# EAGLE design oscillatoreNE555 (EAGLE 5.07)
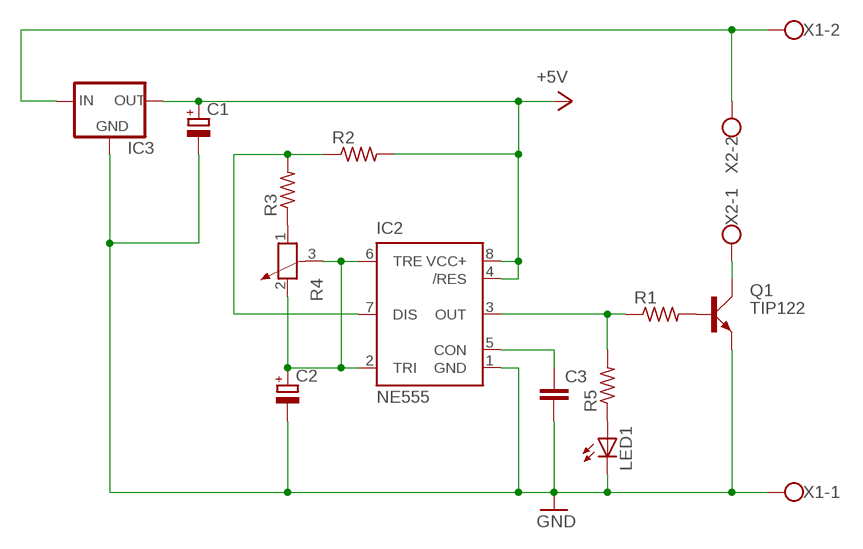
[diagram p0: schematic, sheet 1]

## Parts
C1  CPOL-EUE2.5-7  [E2,5-7]
C2  CPOL-EUE2.5-7  [E2,5-7]
C3  C-EU050-025X075  [C050-025X075]
IC2  NE555  [DIL-08]
IC3  78XXS  [78XXS]
LED1  LED3MM  [LED3MM]
Q1  TIP122  TIP41C  [TO220AV]
R1  R-US_0207/10  [0207/10]
R2  R-US_0207/10  [0207/10]
R3  R-US_0207/10  [0207/10]
R4  POTENTIOMETER_PT-10S  [PT-10S]
R5  R-US_0207/10  [0207/10]
X1  W237-02P  [W237-132]
X2  W237-02P  [W237-132]

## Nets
N$2: Q1.B R1.2
N$3: LED1.A R5.1
N$4: Q1.C X2.1
N$11: C2.+ IC2.2(TRI) IC2.6(TRE) R4.2 R4.3
N$12: R3.1 R4.1
N$13: IC2.7(DIS) R2.1 R3.2
N$17: IC2.3(OUT) R1.1 R5.2
N$19: C3.1 IC2.5(CON)
N$33: IC3.IN X1.2 X2.2
VDD: C1.+ IC2.4(/RES) IC2.8(VCC+) IC3.OUT R2.2 ; supply symbol labelled +5V
VSS: C1.- C2.- C3.2 IC2.1(GND) IC3.GND LED1.K(C) Q1.E X1.1 ; supply symbol labelled GND

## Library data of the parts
C1 C2 = resistor:CPOL-EU: POLARIZED CAPACITOR, European symbol
C3 = resistor:C-EU: CAPACITOR, European symbol
IC2 = st-microelectronics:NE555: General purpose bipolar Timer
IC3 = v-reg:78XXS: VOLTAGE REGULATOR
LED1 = led:LED: LED
Q1 = transistor-power:TIP41C: NPN TRANSISTOR
R1-R3 R5 = resistor:R-US_: RESISTOR, American symbol
R4 = rcl:POTENTIOMETER_: Potentiometer
X1 X2 = con-wago-508:W237-02P: WAGO SREW CLAMP

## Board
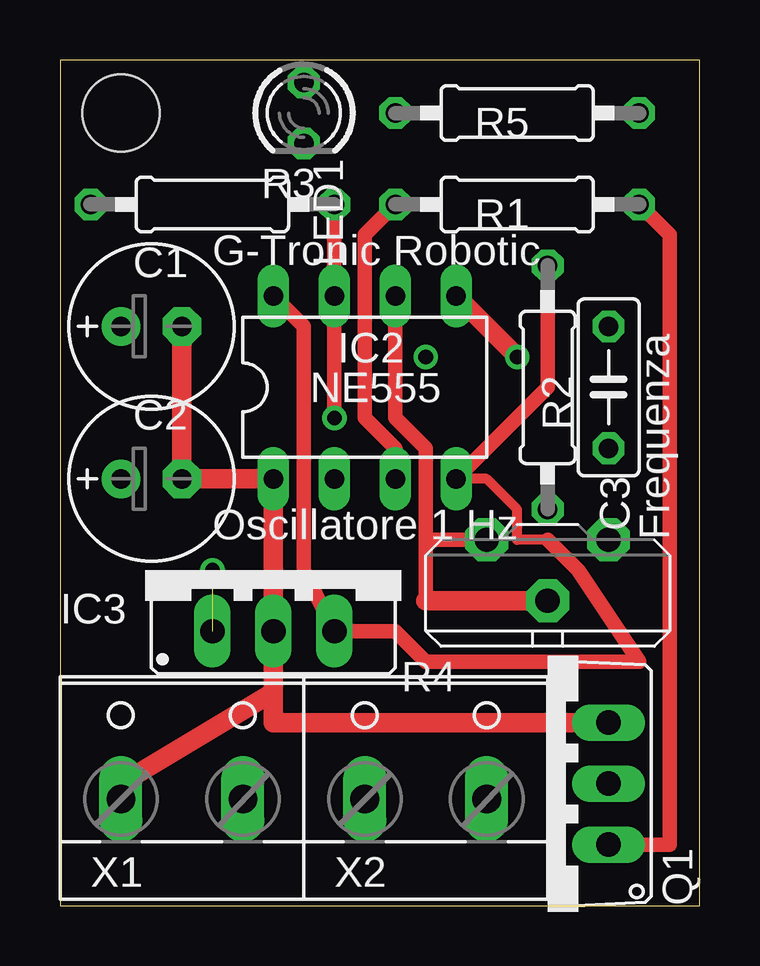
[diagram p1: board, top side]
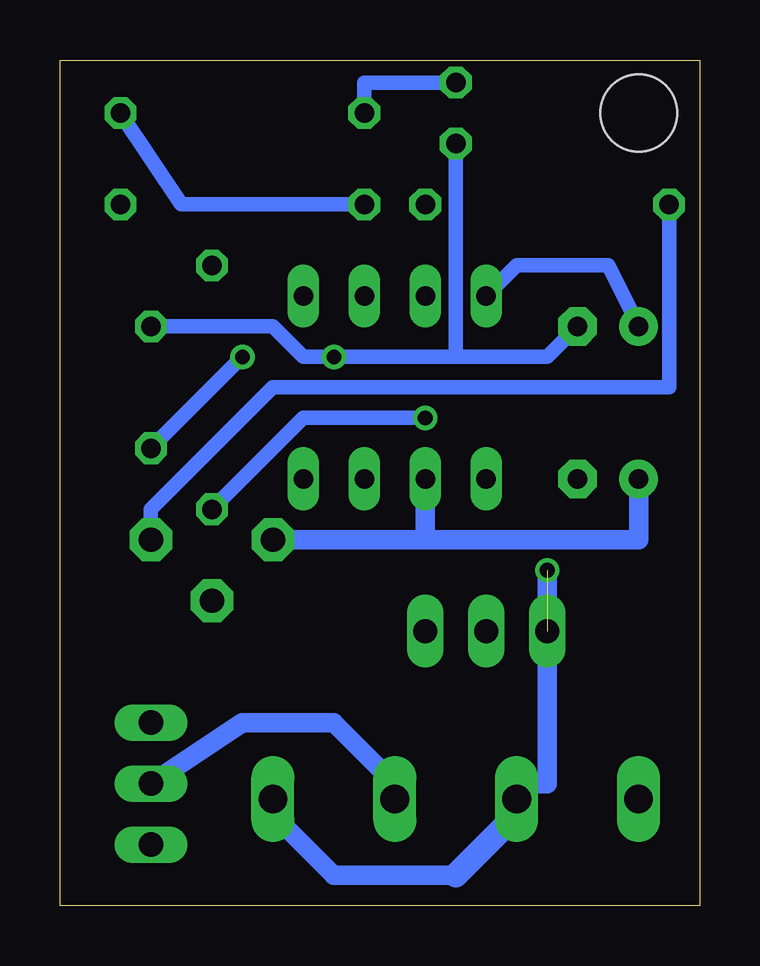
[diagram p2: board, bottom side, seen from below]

Size 26.65 x 35.23 mm. Coordinates in mm from the lower left corner, seen from the top.
Outline: 0,0 26.65,0 26.65,35.23 0,35.23 0,0
Copper layers (1*16): Top 0.035mm / dielectric 1.5mm / Bottom 0.035mm
Design rules "default": minimum track width 10mil, minimum drill 24mil, track to track 8mil, track to pad 8mil, pad to pad 8mil, via to via 8mil, smd to smd 8mil, copper to edge 40mil, drill to drill 8mil, minimum pad ring 10mil, minimum via ring 8mil, stop-mask expansion 4mil, vias tented up to drill 0mil, thermal gap 10mil
Holes 3.2 mm at 2.54,33.02

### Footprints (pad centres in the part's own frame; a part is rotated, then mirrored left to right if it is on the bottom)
E2,5-7 = drill 0.813 pad 1.6 round: + -1.27,0 | drill 0.813 pad 1.6 octagon: - 1.27,0
C050-025X075 = drill 0.813 octagon: 1 -2.54,0; 2 2.54,0
DIL-08 = drill 0.813 long: 1 -3.81,-3.81; 2 -1.27,-3.81; 3 1.27,-3.81; 4 3.81,-3.81; 5 3.81,3.81; 6 1.27,3.81; 7 -1.27,3.81; 8 -3.81,3.81
78XXS = drill 1.016 long: GND 0,-2.54; IN -2.54,-2.54; OUT 2.54,-2.54
LED3MM = drill 0.813 octagon: A -1.27,0; K 1.27,0
TO220AV = drill 1.016 long: B -2.54,-2.54; C 0,-2.54; E 2.54,-2.54
0207/10 = drill 0.813 octagon: 1 -5.08,0; 2 5.08,0
PT-10S = drill 1.016 pad 1.778 octagon: 1 -2.54,-1.27; 2 2.54,-1.27; 3 0,1.27
W237-132 = drill 1.194 long: 1 -2.54,-0.635; 2 2.54,-0.635

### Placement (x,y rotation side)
C1  3.81,24.13 0 top
C2  3.81,17.78 0 top
C3  22.86,21.59 90 top
IC2  12.7,21.59 0 top
IC3  8.89,13.97 0 top
LED1  10.16,33.02 270 top
Q1  20.32,5.08 90 top
R1  19.05,29.21 0 top
R2  20.32,21.59 90 top
R3  6.35,29.21 0 top
R4  20.32,13.97 180 top
R5  19.05,33.02 0 top
X1  5.08,5.08 0 top
X2  15.24,5.08 0 top

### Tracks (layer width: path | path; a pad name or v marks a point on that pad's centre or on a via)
N$2
  Top 0.61: R1.2 25.4,27.94 25.4,2.54 Q1.B
N$3
  Bottom 0.61: LED1.A 13.97,34.29 R5.1
N$4
  Bottom 0.254: X2.1 12.7,5.08
  Bottom 0.813: Q1.C 19.05,7.62 15.24,7.62 12.7,5.08
N$11
  Top 0.61: IC2.6 13.97,20.32 15.24,19.05 15.24,15.24 | 15.24,15.24 15.24,12.7 | R4.2 15.24,15.24
  Top 0.813: 15.24,12.7 R4.3
  Bottom 0.813: 11.43,15.24 IC2.2 | 11.43,15.24 R4.2 | C2.+ 2.54,15.24 11.43,15.24
N$12
  Bottom 0.61: R3.1 1.27,21.59 17.78,21.59 22.86,16.51 R4.1
N$13  (via drill 0.61)
  Top 0.61: v11.43,20.32 IC2.7 R3.2
  Bottom 0.61: v11.43,20.32 16.51,20.32 R2.1
  other vias: 11.43,25.4
N$17
  Top 0.61: IC2.3 13.97,19.05 12.7,20.32 12.7,27.94 R1.1
  Bottom 0.61: R5.2 21.59,29.21 R1.1
N$19  (via drill 0.61)
  Top 0.813: v19.05,22.86 IC2.5
  Bottom 0.61: C3.1 v19.05,22.86
N$33  (via drill 0.61)  (1 unrouted)
  Bottom 0.254: 17.78,3.81 X2.2
  Bottom 0.61: 7.62,5.08 X1.2 7.62,3.81
  Bottom 0.813: v6.35,13.97 6.35,5.08 7.62,5.08 | 17.78,3.81 15.24,1.27 10.16,1.27
  Bottom 1.016: 7.62,3.81 10.16,1.27
VDD
  Top 0.406: 20.32,15.24 19.05,15.24 19.05,16.51 17.78,17.78 IC2.4
  Top 0.61: IC2.4 20.32,21.59 R2.2 | 20.32,15.24 21.59,13.97 24.13,10.16 15.24,10.16 13.97,11.43 IC3.OUT 10.16,13.97 10.16,24.13 IC2.8
  Bottom 0.61: C1.+ 3.81,26.67 7.62,26.67 IC2.8
VSS  (via drill 0.61)
  Top 0.254: X1.1 2.54,5.08
  Top 0.61: 8.89,8.89 IC3.GND
  Top 0.813: C1.- C2.- IC2.1 IC3.GND 8.89,7.62 Q1.E | 2.54,5.08 8.89,8.89
  Bottom 0.61: C3.2 17.78,24.13 16.51,22.86 v15.24,22.86 10.16,22.86 | 10.16,22.86 6.35,22.86 C1.- | 10.16,22.86 LED1.K

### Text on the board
tNames: G-Tronic Robotic | Oscillatore 1 Hz | Frequenza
